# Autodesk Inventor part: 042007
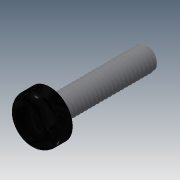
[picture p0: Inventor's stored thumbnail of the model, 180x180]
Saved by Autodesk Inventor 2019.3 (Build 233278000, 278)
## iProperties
Created: 2012-09
Part Number: 042007
Material: Ogólny
Document SubType Name: Modeling
Designer: CADENGINEERING4
Density: 1 g/cm^3
Appearance: Domyślna
Author: CADENGINEERING4
Revision Number: ÈÎºÎ
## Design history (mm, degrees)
feature "Ðý×ª1"
node "Bryła1"
